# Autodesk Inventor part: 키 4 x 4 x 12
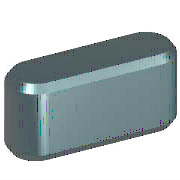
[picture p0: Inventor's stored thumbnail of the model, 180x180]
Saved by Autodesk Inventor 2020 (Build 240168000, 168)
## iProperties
IsCustomPart: 1
Created: 2012-02
Part Number: 키 4 x 4 x 12
Material: 강철, 연강
Description: 키 및 해당 키홈
Document SubType Name: Modeling
Standard: KS B 1311
Designer: mduedu
Standards Organization: KS
Language: ko-KR
Size Designation: 4 x 4 x 12
Categories: <MemberInstance><Categories><Category DisplayName="샤프트 부품" InternalName="7f7aeb1f-a693-4053-b835-cee3144e0d98" Mnemonic="SHFT"><Category DisplayName="키" Interna
Density: 1 g/cm^3
Appearance: 노란색
Author: mduedu
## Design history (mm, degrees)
workplane "Work Plane1"
workplane "Work Plane2"
sketch "스케치1"
  geometry: L1 (2, 2)-(10, 2); L2 (10, -2)-(2, -2); L3 (0, 9.4)-(0, -7.4) reference; L4 (-5, 0)-(30, 0) reference; L5 (12, 0)-(12, 7); A1 r 2 centre (2, 0) between (2, 2) and (2, -2); A2 r 2 centre (10, 0) between (10, -2) and (10, 2)
  constraints: 6 end point, 5 point on circle, 4 tangent, 3 point on line, 2 centre point, 1 horizontal, 1 parallel, 1 perpendicular
  dimensions: "d0" = 2 radius of A1 (= 0.5 x PB); "d13" = 2 radius of A2 (= 0.5 x PB); "d14" = 12 distance between parallel lines of L5 L3 (= NLG)
extrude "본체1" new body sketch "스케치1" taper "d3" = 0 deg; stored distance "d4" = 10
workplane "Work Plane3"
body "Solid1"
chamfer "모따기1" distance "d8" = 0.25 (= PHH); stored, may be unused: second distance "d9" = 0.25 (= PHH), angle "d15" = 45 deg
other parameters: "d1" = -2.5 (= -PNT), "d2" = 1.5 (= PH - PNT), "NLG" = 12 [user parameter; used in 3 equation terms], "PB" = 4 [user parameter; used in 2 equation terms], "PNT" = 2.5 [user parameter; used in 2 equation terms], "PH" = 4 [user parameter; used in 1 equation term], "PHH" = 0.25 [user parameter; used in 2 equation terms], "d10" = 0, "d16" = 0, "d17" = 0, "d18" = 0, "PLB2" = 12 (= NLG) [user parameter], "WDMAX" = 12 [user parameter], "PLB1" = 12 (= NLG) [user parameter], "RR" = 0.08 [user parameter], "PUEB" = 1.8 [user parameter]
